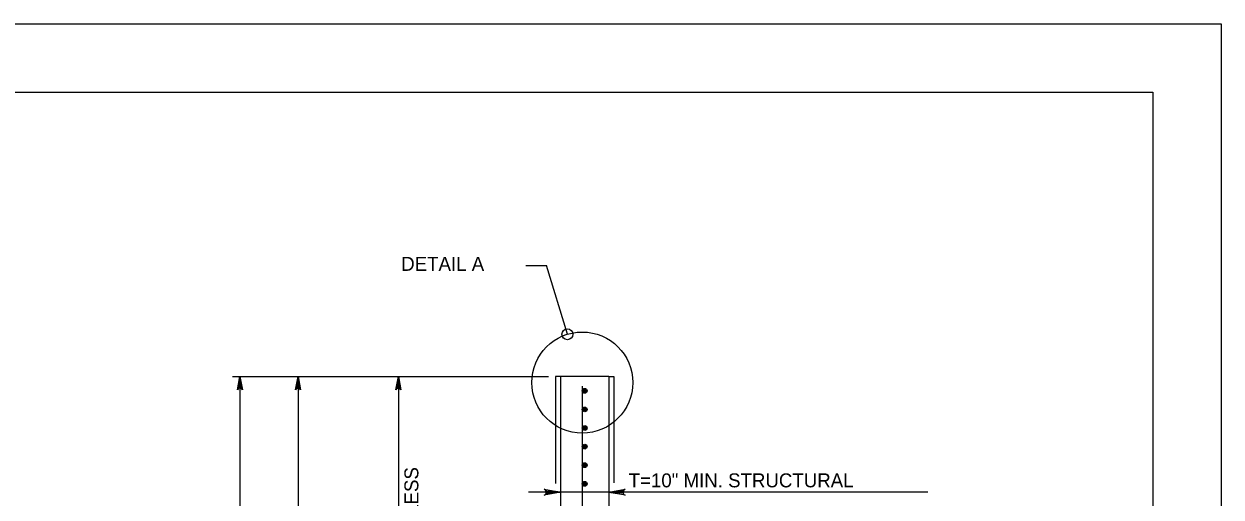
# Model space of a CAD drawing. Extents: x 3385 to 6532, y -616 to 1166.
# Drawn here: x 6020.8 to 6284.3, y 1061.6 to 1165.7 of the extents above; entities that cross this region are included whole.
import ezdxf

# ---------------------------------------------------------------- set-up
doc = ezdxf.new("R2010")
doc.units = 0
for name, color, linetype in [('1', 7, 'Continuous'), ('2', 7, 'Continuous'), ('PLT-BNDY', 7, 'Continuous')]:
    doc.layers.add(name, color=color, linetype=linetype)

msp = doc.modelspace()

# ---------------------------------------------------------------- linework, layer by layer
at = {"layer": '1'}
for p, q in [((6131.28, 1112.52), (6135.83, 1112.52)), ((6140.45, 1097.43), (6135.83, 1112.52)), ((6066.74, 1088.17), (6136.32, 1088.17)), ((6068.35, 1088.17), (6068.35, 921.77)), ((6081.15, 1088.17), (6081.15, 902.75)), ((6103.24, 1088.17), (6103.24, 1011.57)), ((6137.85, 1088.17), (6137.85, 1064.58)), ((6138.91, 1088.17), (6137.85, 1088.17)), ((6149.58, 1088.17), (6138.91, 1088.17)), ((6138.91, 1088.17), (6138.91, 1011.77)), ((6143.71, 1086.04), (6143.71, 1014.68)), ((6149.58, 1088.17), (6149.58, 1011.77)), ((6149.58, 1088.17), (6150.65, 1088.17)), ((6150.65, 1088.17), (6150.65, 1064.74)), ((6219.77, 1062.68), (6131.87, 1062.68))]:
    msp.add_line(p, q, dxfattribs=at)
for points in [[(6068.35, 1088.17), (6068.91, 1085.19), (6068.75, 1085.42), (6068.55, 1085.54), (6068.35, 1085.58), (6068.15, 1085.54), (6067.95, 1085.42), (6067.79, 1085.19), (6068.35, 1088.17), (6067.95, 1085.42), (6068.15, 1085.54), (6068.35, 1088.17), (6068.35, 1085.58), (6068.55, 1085.54), (6068.35, 1088.17), (6068.75, 1085.42)], [(6081.15, 1088.17), (6081.71, 1085.19), (6081.55, 1085.42), (6081.35, 1085.54), (6081.15, 1085.58), (6080.95, 1085.54), (6080.75, 1085.42), (6080.59, 1085.19), (6081.15, 1088.17), (6080.75, 1085.42), (6080.95, 1085.54), (6081.15, 1088.17), (6081.15, 1085.58), (6081.35, 1085.54), (6081.15, 1088.17), (6081.55, 1085.42)], [(6103.24, 1088.17), (6103.79, 1085.19), (6103.64, 1085.42), (6103.44, 1085.54), (6103.24, 1085.58), (6103.04, 1085.54), (6102.84, 1085.42), (6102.68, 1085.19), (6103.24, 1088.17), (6102.84, 1085.42), (6103.04, 1085.54), (6103.24, 1088.17), (6103.24, 1085.58), (6103.44, 1085.54), (6103.24, 1088.17), (6103.64, 1085.42)], [(6103.24, 1088.17), (6103.79, 1085.19), (6103.64, 1085.42), (6103.44, 1085.54), (6103.24, 1085.58), (6103.04, 1085.54), (6102.84, 1085.42), (6102.68, 1085.19), (6103.24, 1088.17), (6102.84, 1085.42), (6103.04, 1085.54), (6103.24, 1088.17), (6103.24, 1085.58), (6103.44, 1085.54), (6103.24, 1088.17), (6103.64, 1085.42)], [(6138.91, 1062.68), (6135.34, 1062), (6135.61, 1062.2), (6135.75, 1062.44), (6135.79, 1062.68), (6135.75, 1062.92), (6135.61, 1063.16), (6135.34, 1063.35), (6138.91, 1062.68), (6135.61, 1063.16), (6135.75, 1062.92), (6138.91, 1062.68), (6135.79, 1062.68), (6135.75, 1062.44), (6138.91, 1062.68), (6135.61, 1062.2)], [(6149.58, 1062.68), (6153.16, 1063.35), (6152.89, 1063.16), (6152.74, 1062.92), (6152.7, 1062.68), (6152.74, 1062.44), (6152.89, 1062.2), (6153.16, 1062), (6149.58, 1062.68), (6152.89, 1062.2), (6152.74, 1062.44), (6149.58, 1062.68), (6152.7, 1062.68), (6152.74, 1062.92), (6149.58, 1062.68), (6152.89, 1063.16)]]:
    msp.add_lwpolyline(points, dxfattribs=at)
for centre, radius in [((6143.72, 1086.8), 11.12), ((6140.45, 1097.43), 1.2), ((6144.25, 1084.97), 0.533), ((6144.25, 1084.97), 0.4), ((6144.25, 1084.97), 0.267), ((6144.25, 1084.97), 0.133), ((6144.25, 1080.89), 0.533), ((6144.25, 1080.89), 0.4), ((6144.25, 1080.89), 0.267), ((6144.25, 1080.89), 0.133), ((6144.25, 1076.8), 0.533), ((6144.25, 1076.8), 0.4), ((6144.25, 1076.8), 0.267), ((6144.25, 1076.8), 0.133), ((6144.25, 1072.71), 0.533), ((6144.25, 1072.71), 0.4), ((6144.25, 1072.71), 0.267), ((6144.25, 1072.71), 0.133), ((6144.25, 1068.62), 0.533), ((6144.25, 1068.62), 0.4), ((6144.25, 1068.62), 0.267), ((6144.25, 1068.62), 0.133), ((6144.25, 1064.53), 0.533), ((6144.25, 1064.53), 0.4), ((6144.25, 1064.53), 0.267), ((6144.25, 1064.53), 0.133)]:
    msp.add_circle(centre, radius, dxfattribs=at)
at = {"layer": '2'}
for p, q in [((5483.34, 1150.69), (6269.34, 1150.69)), ((6269.34, 1150.69), (6269.34, 586.69))]:
    msp.add_line(p, q, dxfattribs=at)
at = {"layer": 'PLT-BNDY'}
msp.add_lwpolyline([(5443.34, 1165.69), (6284.34, 1165.69), (6284.34, 571.69), (5443.34, 571.69)], close=True, dxfattribs=at)

# ---------------------------------------------------------------- texts
at = {"layer": '1'}
for s, p in [('DETAIL A', (6103.86, 1111.38)), ('T=10" MIN. STRUCTURAL', (6153.93, 1063.75))]:
    msp.add_text(s, height=3.072, dxfattribs=at).set_placement(p)
msp.add_text('OR WALL HEIGHT IF LESS', height=3.0721, rotation=90, dxfattribs=at).set_placement((6107.64, 1016.61))

doc.saveas('drawing.dxf')
